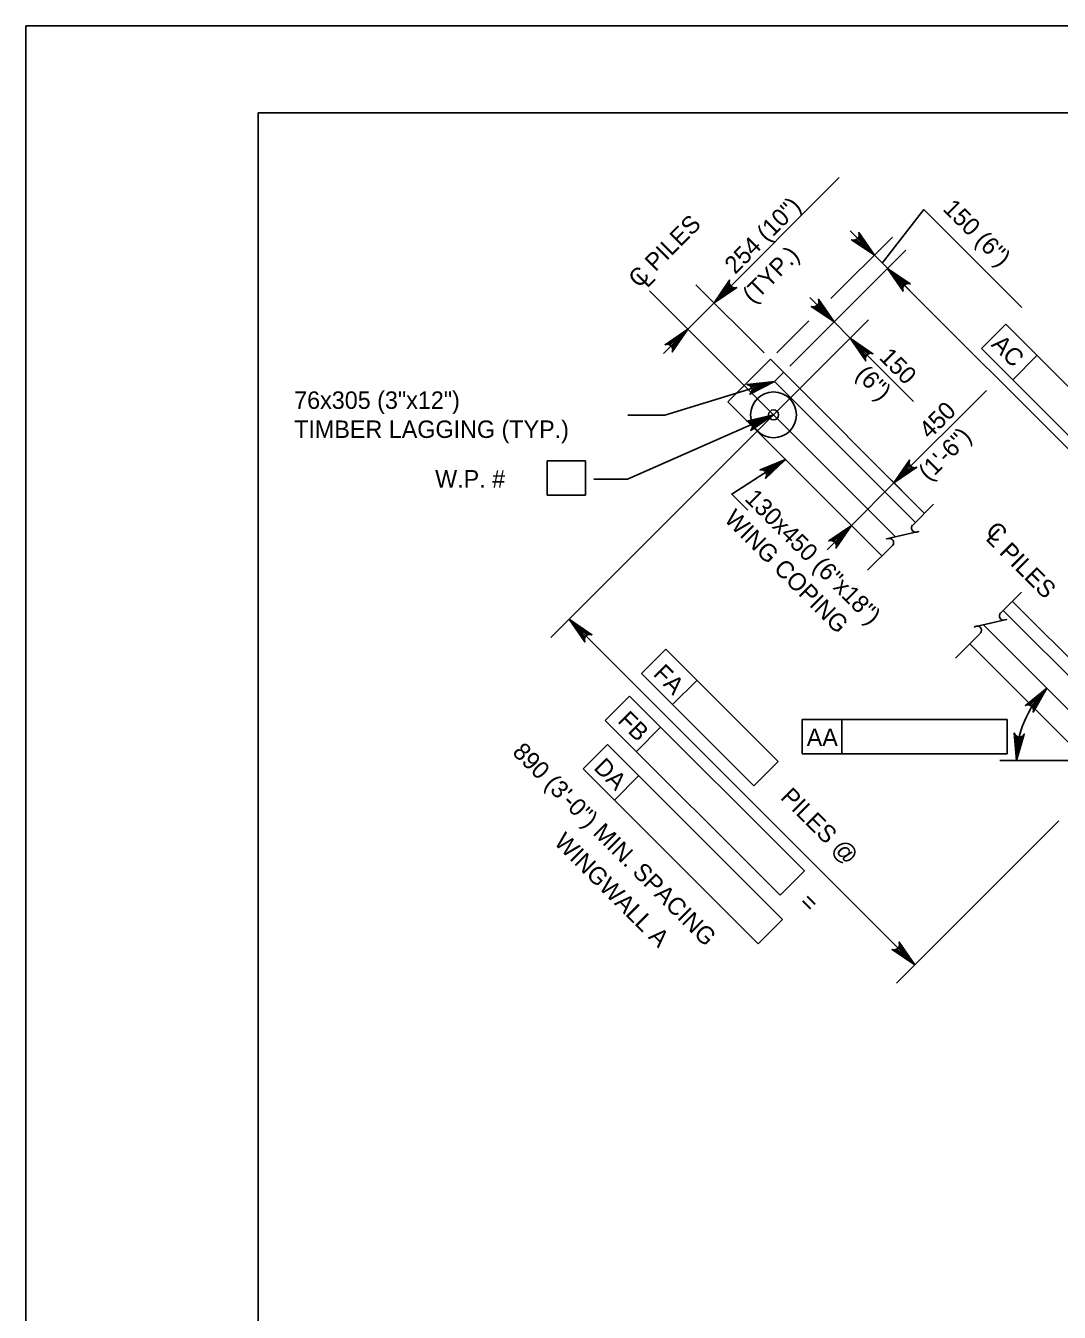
# Model space of a CAD drawing. Extents: x 635440 to 640306, y 296653 to 298484.
# Drawn here: x 638435.5 to 638613.2, y 298214.2 to 298435.5 of the extents above; entities that cross this region are included whole.
import ezdxf

# ---------------------------------------------------------------- set-up
doc = ezdxf.new("R2010")
doc.units = 0
for name, color, linetype in [('2', 7, 'Continuous'), ('4', 7, 'Continuous'), ('5', 7, 'Continuous'), ('52', 7, 'Continuous'), ('PLT-BNDY', 7, 'Continuous')]:
    doc.layers.add(name, color=color, linetype=linetype)

msp = doc.modelspace()

# ---------------------------------------------------------------- linework, layer by layer
at = {"layer": '2'}
for p, q in [((638475.46, 297856.46), (638475.46, 298420.46)), ((638475.46, 298420.46), (639261.46, 298420.46)), ((638563.54, 298378.1), (638556.23, 298370.8)), ((638590.03, 298351.61), (638563.54, 298378.1)), ((638582.73, 298344.3), (638556.23, 298370.8)), ((638625.14, 298316.5), (638605.15, 298336.5)), ((638620.86, 298306.16), (638597.84, 298329.19))]:
    msp.add_line(p, q, dxfattribs=at)
at = {"layer": '4'}
for p, q in [((638565.8, 298375.84), (638564.23, 298374.28)), ((638588.47, 298350.04), (638564.23, 298374.28)), ((638629.32, 298309.2), (638603.58, 298334.93))]:
    msp.add_line(p, q, dxfattribs=at)
msp.add_circle((638564.08, 298368.55), 3.94, dxfattribs=at)
at = {"layer": '5'}
for p, q in [((638553.85, 298387.79), (638575.39, 298409.35)), ((638582.76, 298394.65), (638589.95, 298403.84)), ((638589.95, 298403.84), (638606.78, 298387.01)), ((638573.96, 298388.53), (638584.55, 298399.12)), ((638581.42, 298395.99), (638577.25, 298400.17)), ((638566.89, 298376.93), (638586.82, 298396.86)), ((638586.64, 298390.77), (638581.42, 298395.99)), ((638643.03, 298334.38), (638583.68, 298393.73)), ((638562.45, 298379.19), (638550.71, 298390.93)), ((638586.47, 298390.94), (638588.56, 298388.86)), ((638585.07, 298347.57), (638542.76, 298389.87)), ((638574.48, 298384.52), (638570.3, 298388.7)), ((638549.34, 298383.29), (638553.85, 298387.8)), ((638566.89, 298376.93), (638577.61, 298387.66)), ((638580.39, 298384.87), (638525.8, 298330.28)), ((638564.63, 298379.19), (638570.13, 298384.7)), ((638574.48, 298384.52), (638577.26, 298381.74)), ((638604.04, 298384.12), (638599.86, 298379.95)), ((638604.04, 298384.12), (638634.11, 298354.06)), ((638549.34, 298383.29), (638545.17, 298379.12)), ((638577.26, 298381.74), (638588.14, 298370.87)), ((638599.86, 298379.95), (638629.93, 298349.88)), ((638609.39, 298378.78), (638605.21, 298374.6)), ((638584.79, 298356.86), (638600.68, 298372.75)), ((638525.17, 298354.72), (638525.17, 298360.63)), ((638525.17, 298360.63), (638531.76, 298360.63)), ((638531.76, 298354.72), (638531.76, 298360.63)), ((638584.35, 298357.3), (638587.92, 298353.72)), ((638531.76, 298354.72), (638525.17, 298354.72)), ((638577.48, 298349.55), (638584.79, 298356.86)), ((638591.59, 298353.17), (638588.01, 298349.58)), ((638577.48, 298349.55), (638573.3, 298345.37)), ((638577.04, 298349.99), (638580.61, 298346.42)), ((638584.57, 298346.15), (638580.25, 298341.82)), ((638606.71, 298338.06), (638603.13, 298334.48)), ((638588.37, 298273.97), (638528.94, 298333.41)), ((638599.69, 298331.04), (638595.37, 298326.72)), ((638625.74, 298306.89), (638600.17, 298332.46)), ((638545.55, 298328.25), (638541.37, 298324.07)), ((638545.55, 298328.25), (638564.85, 298308.95)), ((638541.37, 298324.07), (638560.67, 298304.77)), ((638550.9, 298322.9), (638546.72, 298318.73)), ((638539.31, 298320.19), (638535.14, 298316.01)), ((638539.31, 298320.19), (638569.38, 298290.12)), ((638535.14, 298316.01), (638565.2, 298285.94)), ((638568.98, 298316.17), (638604.28, 298316.17)), ((638568.98, 298310.26), (638568.98, 298316.17)), ((638575.82, 298310.26), (638575.82, 298316.17)), ((638604.28, 298316.17), (638604.28, 298310.26)), ((638544.66, 298314.84), (638540.48, 298310.66)), ((638535.53, 298311.85), (638531.36, 298307.67)), ((638535.53, 298311.85), (638565.6, 298281.78)), ((638564.85, 298308.95), (638560.67, 298304.77)), ((638604.28, 298310.26), (638568.98, 298310.26)), ((638895.93, 298309.12), (638603.01, 298309.12)), ((638531.36, 298307.67), (638561.43, 298277.6)), ((638540.88, 298306.5), (638536.71, 298302.32)), ((638613.16, 298298.76), (638585.24, 298270.84)), ((638569.38, 298290.12), (638565.2, 298285.94)), ((638565.6, 298281.78), (638561.43, 298277.6))]:
    msp.add_line(p, q, dxfattribs=at)
for points in [[(638581.42, 298395.99), (638577.51, 298398.67), (638577.94, 298398.59), (638578.29, 298398.68), (638578.55, 298398.86), (638578.73, 298399.12), (638578.82, 298399.47), (638578.74, 298399.9), (638581.42, 298395.99), (638578.82, 298399.47), (638578.73, 298399.12), (638581.42, 298395.99), (638578.55, 298398.86), (638578.29, 298398.68), (638581.42, 298395.99), (638577.94, 298398.59)], [(638583.68, 298393.73), (638587.6, 298391.05), (638587.17, 298391.13), (638586.82, 298391.04), (638586.56, 298390.85), (638586.37, 298390.6), (638586.28, 298390.24), (638586.36, 298389.81), (638583.68, 298393.73), (638586.28, 298390.24), (638586.37, 298390.6), (638583.68, 298393.73), (638586.56, 298390.85), (638586.82, 298391.04), (638583.68, 298393.73), (638587.17, 298391.13)], [(638553.85, 298387.79), (638556.52, 298391.71), (638556.45, 298391.28), (638556.54, 298390.93), (638556.72, 298390.67), (638556.98, 298390.48), (638557.33, 298390.4), (638557.76, 298390.47), (638553.85, 298387.79), (638557.33, 298390.4), (638556.98, 298390.48), (638553.85, 298387.79), (638556.72, 298390.67), (638556.54, 298390.93), (638553.85, 298387.79), (638556.45, 298391.28)], [(638574.48, 298384.52), (638570.57, 298387.2), (638571, 298387.12), (638571.35, 298387.21), (638571.61, 298387.4), (638571.79, 298387.66), (638571.88, 298388.01), (638571.8, 298388.44), (638574.48, 298384.52), (638571.88, 298388.01), (638571.79, 298387.66), (638574.48, 298384.52), (638571.61, 298387.4), (638571.35, 298387.21), (638574.48, 298384.52), (638571, 298387.12)], [(638549.34, 298383.29), (638546.66, 298379.38), (638546.74, 298379.81), (638546.65, 298380.16), (638546.47, 298380.42), (638546.21, 298380.6), (638545.86, 298380.69), (638545.43, 298380.61), (638549.34, 298383.29), (638545.86, 298380.69), (638546.21, 298380.6), (638549.34, 298383.29), (638546.47, 298380.42), (638546.65, 298380.16), (638549.34, 298383.29), (638546.74, 298379.81)], [(638577.26, 298381.74), (638581.18, 298379.06), (638580.75, 298379.14), (638580.39, 298379.05), (638580.14, 298378.87), (638579.95, 298378.61), (638579.86, 298378.25), (638579.94, 298377.83), (638577.26, 298381.74), (638579.86, 298378.25), (638579.95, 298378.61), (638577.26, 298381.74), (638580.14, 298378.87), (638580.39, 298379.05), (638577.26, 298381.74), (638580.75, 298379.14)], [(638564.23, 298374.28), (638545.36, 298368.52), (638539.02, 298368.52)], [(638564.23, 298374.28), (638560.03, 298372.08), (638560.3, 298372.43), (638560.39, 298372.78), (638560.35, 298373.09), (638560.2, 298373.38), (638559.94, 298373.62), (638559.52, 298373.75), (638564.23, 298374.28), (638559.94, 298373.62), (638560.2, 298373.38), (638564.23, 298374.28), (638560.35, 298373.09), (638560.39, 298372.78), (638564.23, 298374.28), (638560.3, 298372.43)], [(638564.08, 298368.55), (638538.96, 298357.51), (638533.15, 298357.51)], [(638566.15, 298360.88), (638556.9, 298354.93), (638559.68, 298352.16)], [(638584.79, 298356.86), (638587.47, 298360.77), (638587.39, 298360.34), (638587.48, 298359.99), (638587.66, 298359.73), (638587.92, 298359.55), (638588.27, 298359.46), (638588.7, 298359.53), (638584.79, 298356.86), (638588.27, 298359.46), (638587.92, 298359.55), (638584.79, 298356.86), (638587.66, 298359.73), (638587.48, 298359.99), (638584.79, 298356.86), (638587.39, 298360.34)], [(638577.48, 298349.55), (638574.8, 298345.63), (638574.88, 298346.06), (638574.79, 298346.42), (638574.61, 298346.67), (638574.35, 298346.86), (638574, 298346.95), (638573.57, 298346.87), (638577.48, 298349.55), (638574, 298346.95), (638574.35, 298346.86), (638577.48, 298349.55), (638574.61, 298346.67), (638574.79, 298346.42), (638577.48, 298349.55), (638574.88, 298346.06)], [(638588.69, 298348.39), (638589.04, 298348.47), (638583.5, 298347.21), (638583.87, 298347.29)], [(638528.94, 298333.41), (638532.85, 298330.73), (638532.42, 298330.81), (638532.07, 298330.72), (638531.81, 298330.54), (638531.63, 298330.28), (638531.54, 298329.93), (638531.61, 298329.5), (638528.94, 298333.41), (638531.54, 298329.93), (638531.63, 298330.28), (638528.94, 298333.41), (638531.81, 298330.54), (638532.07, 298330.72), (638528.94, 298333.41), (638532.42, 298330.81)], [(638603.81, 298333.29), (638604.16, 298333.37), (638598.62, 298332.1), (638598.99, 298332.19)], [(638611.07, 298321.57), (638608.73, 298317.44), (638608.77, 298317.88), (638608.65, 298318.22), (638608.45, 298318.46), (638608.17, 298318.62), (638607.81, 298318.68), (638607.39, 298318.57), (638611.07, 298321.57), (638607.81, 298318.68), (638608.17, 298318.62), (638611.07, 298321.57), (638608.45, 298318.46), (638608.65, 298318.22), (638611.07, 298321.57), (638608.77, 298317.88)], [(638605.87, 298309.11), (638605.48, 298313.84), (638605.69, 298313.45), (638605.98, 298313.24), (638606.29, 298313.15), (638606.6, 298313.17), (638606.93, 298313.32), (638607.21, 298313.66), (638605.87, 298309.11), (638606.93, 298313.32), (638606.6, 298313.17), (638605.87, 298309.11), (638606.29, 298313.15), (638605.98, 298313.24), (638605.87, 298309.11), (638605.69, 298313.45)], [(638588.37, 298273.97), (638584.46, 298276.65), (638584.89, 298276.57), (638585.24, 298276.66), (638585.5, 298276.85), (638585.68, 298277.1), (638585.77, 298277.46), (638585.7, 298277.89), (638588.37, 298273.97), (638585.77, 298277.46), (638585.68, 298277.1), (638588.37, 298273.97), (638585.5, 298276.85), (638585.24, 298276.66), (638588.37, 298273.97), (638584.89, 298276.57)]]:
    msp.add_lwpolyline(points, dxfattribs=at)
for points in [[(638579.68, 298398.42), (638578.99, 298397.73), (638581.42, 298395.99)], [(638586.12, 298391.99), (638585.42, 298391.29), (638583.68, 298393.73)], [(638555.59, 298390.23), (638556.28, 298389.54), (638553.85, 298387.8)], [(638572.74, 298386.96), (638572.04, 298386.26), (638574.48, 298384.52)], [(638546.91, 298381.55), (638547.6, 298380.86), (638549.34, 298383.29)], [(638579.7, 298380), (638579, 298379.3), (638577.26, 298381.74)], [(638564.23, 298374.28), (638561.34, 298373.65), (638561.48, 298373.18)], [(638586.53, 298359.29), (638587.22, 298358.6), (638584.79, 298356.86)], [(638575.04, 298347.81), (638575.74, 298347.11), (638577.48, 298349.55)], [(638531.37, 298331.67), (638530.68, 298330.98), (638528.94, 298333.41)], [(638586.63, 298276.41), (638585.94, 298275.71), (638588.37, 298273.97)]]:
    msp.add_lwpolyline(points, close=True, dxfattribs=at)
msp.add_circle((638564.08, 298368.55), 0.85, dxfattribs=at)
for centre, radius, start, end in [((638588.51, 298349.08), 0.71, 135, 285), ((638584.03, 298346.6), 0.71, 320.3286, 102.8672), ((638603.63, 298333.98), 0.71, 135, 285), ((638599.15, 298331.5), 0.71, 320.3286, 102.8672), ((638623.39, 298309.12), 17.52, 134.7007, 179.9991)]:
    msp.add_arc(centre, radius, start, end, dxfattribs=at)
at = {"layer": '52'}
for points in [[(638564.08, 298368.55), (638560.16, 298365.88), (638560.39, 298366.25), (638560.44, 298366.61), (638560.36, 298366.92), (638560.19, 298367.18), (638559.89, 298367.4), (638559.46, 298367.48), (638564.08, 298368.55), (638559.89, 298367.4), (638560.19, 298367.18), (638564.08, 298368.55), (638560.36, 298366.92), (638560.44, 298366.61), (638564.08, 298368.55), (638560.39, 298366.25)], [(638566.15, 298360.88), (638562.7, 298357.62), (638562.87, 298358.02), (638562.86, 298358.39), (638562.73, 298358.68), (638562.52, 298358.91), (638562.19, 298359.08), (638561.76, 298359.09), (638566.15, 298360.88), (638562.19, 298359.08), (638562.52, 298358.91), (638566.15, 298360.88), (638562.73, 298358.68), (638562.86, 298358.39), (638566.15, 298360.88), (638562.87, 298358.02)]]:
    msp.add_lwpolyline(points, dxfattribs=at)
at = {"layer": 'PLT-BNDY'}
msp.add_lwpolyline([(638435.46, 298435.46), (639276.46, 298435.46), (639276.46, 297841.46), (638435.46, 297841.46)], close=True, dxfattribs=at)

# ---------------------------------------------------------------- texts
at = {"layer": '5'}
for s, height, rotation, p in [('254 (10")', 3, 45, (638557.47, 298392.6)), ('150 (6")', 3, 315, (638593.06, 298403.82)), ('C PILES', 3, 45, (638540.93, 298390.23)), ('(TYP.)', 3, 45, (638560.54, 298387.53)), ('L', 3, 45, (638542.33, 298390.25)), ('AC', 3, 314.9382, (638601.38, 298380.49)), ('150', 3, 315, (638582.08, 298378.27)), ('(6")', 3, 315, (638578.02, 298375.26)), ('450', 3, 45, (638590.94, 298364.25)), ('(1\'-6")', 3, 45, (638590.8, 298357.03)), ('130x450 (6"x18")', 3.0001, 315, (638558.97, 298353.98)), ('WING COPING', 3.0001, 315, (638555.43, 298350.45)), ('L PILES', 3, 315, (638600.4, 298347.14)), ('C', 3, 315, (638600.39, 298348.4)), ('FA', 3, 314.9382, (638543.21, 298323.85)), ('FB', 3, 314.9382, (638537.14, 298315.81)), ('890 (3\'-0") MIN. SPACING', 3.0001, 315, (638519, 298310.37)), ('DA', 3, 314.9382, (638532.98, 298307.72)), ('PILES @', 3, 314.9382, (638565.1, 298302.64)), ('WINGWALL A', 3, 315, (638526.16, 298294.89)), ('=', 3, 314.9382, (638568.33, 298284.51))]:
    msp.add_text(s, height=height, rotation=rotation, dxfattribs=at).set_placement(p)
for s, height, p in [('76x305 (3"x12")', 3.0001, (638481.63, 298369.58)), ('TIMBER LAGGING (TYP.)', 3.0001, (638481.63, 298364.58)), ('W.P. # ', 3, (638505.88, 298356.05)), ('AA', 3, (638569.79, 298311.61))]:
    msp.add_text(s, height=height, dxfattribs=at).set_placement(p)

doc.saveas('drawing.dxf')
